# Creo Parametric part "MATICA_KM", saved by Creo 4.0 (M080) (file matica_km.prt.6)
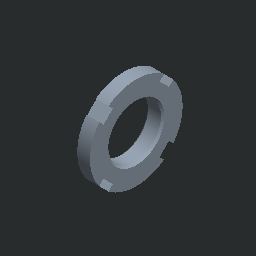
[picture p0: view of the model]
Units: Custom; MM, KILOGRAM, SECS
Materials in the file: OCEL, OCEL_N

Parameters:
  PTC_MATERIAL_NAME = "OCEL"
  NAZOV = "MATICA_KM"

Other parameters: HMOTNOST, HUSTOTA

Created from: KRUH_MATICE.PRT

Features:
  1. datum plane "DTM11"
  2. pattern
  3. datum plane "DTM12"
  4. cut
  5. cut
  6. cut
  7. cut
  8. datum plane "DTM14"
  9. cut

Other named items: THRU

Named dimensions: D1_zavitu, D_zavitu, male_b

Layers: 1, 2, 3, 4, 5, 6, 7, 8, 9, 10, 11, 12, 13, 14, 15, 16, 17, 18, 19, 20, 21, 22, 23, 24, 25, 26, 27, 28, 29, 30, 31, 32

Family table entries: GENERIC, MATICA_KM3, MATICA_KM, value(d_val), 2/<, 2/8, value(i_val), MATICA_KM4, MATICA_KM, !/4, 2/@, 2/:, MATICA_KM5, MATICA_KM, !/9, 2/C, 2/@, MATICA_KM6, MATICA_KM, !/>, 2/C, MATICA_KM7, MATICA_KM, 2/J, 2/F, 2/ , MATICA_KM8, MATICA_KM, !/D, 2/M, 2/I, 2/", MATICA_KM9, MATICA_KM, 2/L, 2/$, MATICA_KM10, MATICA_KM, !/I, 2/&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

Surfaces: 14 plane, 6 cone, 5 cylinder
